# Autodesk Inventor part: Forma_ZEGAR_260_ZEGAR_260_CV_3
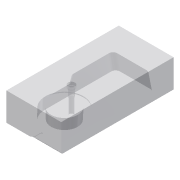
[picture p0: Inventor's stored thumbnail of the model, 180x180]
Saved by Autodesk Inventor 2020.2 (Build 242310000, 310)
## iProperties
Created: 2015-01
Part Number: Forma_ZEGAR_260_ZEGAR_260_CV_3
Material: Ogólny
Document SubType Name: Modeling
Designer: F.Stasiak
Density: 1 g/cm^3
Appearance: Domyślna
Catalog Web Link: www.expertbooks.pl
Manager: www.cadconsulting.pl
Company: Fabian Stasiak CAD Consulting
Author: F.Stasiak
Subject: Zbiór ćwiczeń. Autodesk Inventor 2020. Kurs Professional
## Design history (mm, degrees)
node "Forma_ZEGAR_260_ZEGAR_260_CV_Base"
feature "Rzeźbienie3"
feature "Bryła5::Forma_ZEGAR_260_ZEGAR_260_CV_Base"
tag "Bryła wyprowadzona1"
node "Bryła1"
feature "Forma_ZEGAR_260_ZEGAR_260_CV_Base_Bodies"
feature "Powierzchnia3"
body "Srf3"
